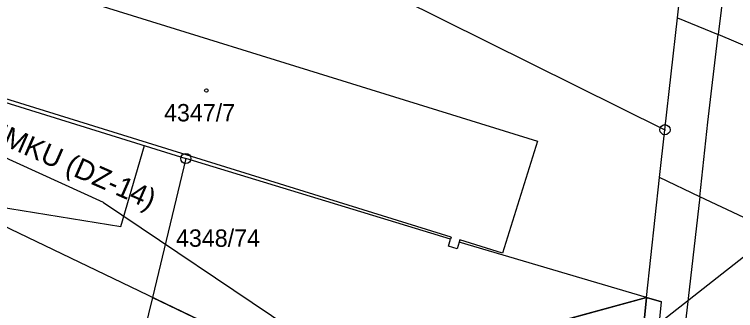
# Model space of a CAD drawing. Extents: x -735036 to -734743, y -1144813 to -1144181.
# Drawn here: x -734893.7 to -734823.1, y -1144501.3 to -1144472.3 of the extents above; entities that cross this region are included whole.
import ezdxf

# ---------------------------------------------------------------- set-up
doc = ezdxf.new("R2010")
doc.units = 0
for name, color, linetype in [('hranice pl. určené SŽDC', 7, 'Continuous'), ('Katastr_HRANICE DRÁHY', 7, 'Continuous'), ('Katastr_Hranice parcel', 7, 'Continuous'), ('Katastr_Parcelní čísla', 7, 'Continuous'), ('Katastr_pozemek_ČD_šrafy', 7, 'Continuous'), ('Katastr_Slučkované čáry', 7, 'Continuous'), ('Katastr_Značky kultur', 7, 'Continuous'), ('ZÁBORY_dočasné', 7, 'Continuous'), ('ZÁBORY_dočasné_šrafy', 7, 'Continuous')]:
    doc.layers.add(name, color=color, linetype=linetype)

msp = doc.modelspace()

# ---------------------------------------------------------------- linework, layer by layer
at = {"layer": 'hranice pl. určené SŽDC'}
for p, q in [((-734883.27, -1144493.05), (-734880.96, -1144485.12)), ((-734900.35, -1144490.28), (-734883.27, -1144493.05))]:
    msp.add_line(p, q, dxfattribs=at)
at = {"layer": 'Katastr_HRANICE DRÁHY'}
for p in [(-734861.21, -1144468.1), (-734830.54, -1144488.25)]:
    msp.add_line(p, (-734830.02, -1144483.57), dxfattribs=at)
for points in [[(-734831.84, -1144499.97), (-734830.54, -1144488.25)], [(-734832.95, -1144511.4), (-734831.84, -1144499.97)]]:
    msp.add_lwpolyline(points, dxfattribs=at)
at = {"layer": 'Katastr_Hranice parcel'}
msp.add_line((-734830.02, -1144483.57), (-734828.81, -1144472.64), dxfattribs=at)
for points in [[(-734828.81, -1144472.64), (-734827.3, -1144458.97)], [(-734902.72, -1144466.02), (-734842.51, -1144484.69)], [(-734828.81, -1144472.64), (-734824.8, -1144474.27)], [(-734917.71, -1144473.71), (-734876.91, -1144486.38)], [(-734819.07, -1144476.7), (-734824.8, -1144474.27)], [(-734850.95, -1144494.07), (-734906.11, -1144476.96)], [(-734865.5, -1144507.03), (-734912.56, -1144484.42)], [(-734842.51, -1144484.69), (-734845.92, -1144495.63)], [(-734851.02, -1144494.29), (-734876.91, -1144486.38)], [(-734826.61, -1144490.15), (-734830.54, -1144488.25)], [(-734819.59, -1144493.44), (-734826.61, -1144490.15)], [(-734851.22, -1144494.96), (-734851.02, -1144494.29)], [(-734850.95, -1144494.07), (-734851.02, -1144494.29)], [(-734850.09, -1144494.34), (-734850.16, -1144494.56)], [(-734845.92, -1144495.63), (-734850.09, -1144494.34)], [(-734850.37, -1144495.22), (-734851.22, -1144494.96)], [(-734850.16, -1144494.56), (-734850.37, -1144495.22)], [(-734831.84, -1144499.97), (-734850.16, -1144494.56)]]:
    msp.add_lwpolyline(points, dxfattribs=at)
at = {"layer": 'Katastr_pozemek_ČD_šrafy'}
for points in [[(-734850.16, -1144494.56), (-734850.37, -1144495.22), (-734851.22, -1144494.96), (-734851.02, -1144494.29), (-734876.91, -1144486.38), (-734880.187, -1144499.973), (-734865.5, -1144507.03), (-734862.79, -1144507.52), (-734852.42, -1144508.98), (-734833.68, -1144511.64), (-734832.99, -1144511.73), (-734832.95, -1144511.4), (-734831.84, -1144499.97), (-734850.16, -1144494.56)], [(-734868.03, -1144506.57), (-734865.5, -1144507.03), (-734880.187, -1144499.973), (-734881.31, -1144504.63), (-734882.78, -1144515.44), (-734872.29, -1144521), (-734870.33, -1144522.02), (-734868.03, -1144506.57)]]:
    msp.add_lwpolyline(points, dxfattribs=at)
at = {"layer": 'Katastr_Slučkované čáry'}
for points in [[(-734823.12, -1144460.47), (-734824.8, -1144474.27)], [(-734825.84, -1144482.82), (-734824.8, -1144474.27)], [(-734826.61, -1144490.15), (-734825.84, -1144482.82)], [(-734826.61, -1144490.15), (-734830.38, -1144523.1)]]:
    msp.add_lwpolyline(points, dxfattribs=at)
at = {"layer": 'Katastr_Značky kultur'}
for p, q in [((-734830.07, -1144483.57), (-734829.97, -1144483.57)), ((-734876.96, -1144486.38), (-734876.86, -1144486.38))]:
    msp.add_line(p, q, dxfattribs=at)
for centre, radius in [((-734874.9, -1144479.74), 0.175), ((-734830.02, -1144483.57), 0.499), ((-734876.91, -1144486.38), 0.499)]:
    msp.add_circle(centre, radius, dxfattribs=at)
at = {"layer": 'ZÁBORY_dočasné'}
for p, q in [((-734884.98, -1144490.683), (-734923.443, -1144473.129)), ((-734810.273, -1144486.527), (-734831.445, -1144503.169)), ((-734884.98, -1144490.683), (-734860.304, -1144507.242)), ((-734857.053, -1144506.856), (-734831.84, -1144499.97)), ((-734831.84, -1144499.97), (-734832.99, -1144511.73)), ((-734831.84, -1144499.97), (-734830.375, -1144500.403))]:
    msp.add_line(p, q, dxfattribs=at)
msp.add_lwpolyline([(-734831.496, -1144511.942), (-734830.375, -1144500.403)], dxfattribs=at)
at = {"layer": 'ZÁBORY_dočasné_šrafy'}
for points in [[(-734857.053, -1144506.856), (-734869.357, -1144505.177), (-734865.5, -1144507.03), (-734852.42, -1144508.98), (-734832.99, -1144511.73), (-734831.84, -1144499.97), (-734857.053, -1144506.856)], [(-734830.375, -1144500.403), (-734831.84, -1144499.97), (-734832.99, -1144511.73), (-734834.23, -1144521.36), (-734832.801, -1144522.006), (-734832.742, -1144521.55), (-734831.496, -1144511.942), (-734830.375, -1144500.403)]]:
    msp.add_lwpolyline(points, dxfattribs=at)

# ---------------------------------------------------------------- texts
at = {"layer": 'Katastr_Parcelní čísla'}
for s, p in [('4347/7', (-734879.043, -1144482.76)), ('4348/74', (-734877.873, -1144495.02))]:
    msp.add_text(s, height=1.7, dxfattribs=at).set_placement(p)
at = {"layer": 'ZÁBORY_dočasné'}
msp.add_text('DOČASNÝ ZÁBOR POZEMKU (DZ-14)', height=2, rotation=336.28002, dxfattribs=at).set_placement((-734923.526, -1144472.474))

doc.saveas('drawing.dxf')
